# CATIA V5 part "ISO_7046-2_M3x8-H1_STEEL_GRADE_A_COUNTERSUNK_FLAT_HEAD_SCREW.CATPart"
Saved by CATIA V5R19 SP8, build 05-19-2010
Part number: ISO 7046-2 Vis M3x8-H1 Tête cruciforme fraisée à 90°
Definition: ISO 7046-2 Vis M3x8-H1 Tête cruciforme fraisée à 90°
Nomenclature: 70522
Publications: "Mating Edge", "Axis"
Bounding box of the stored display mesh (mm): x -8 to 0, y -2.741 to 2.741, z -2.75 to 2.75
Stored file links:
  D:\Documents\1_Travail\1 - ac-limoges.fr\ac-limoges.fr\Emmanuel Maynard - STI2D_Turgot\1 - IT-I2D\Activités_IT_Première\IT_3_Abris_bus\Maquettes numériques\Abribus_eleve\ISO_7046-2_M3x8-H1_STEEL_GRADE_A_COUNTERSUNK_FLAT_HEAD_SCREW.CATPart
  C:\MechanicalStandardParts\EN_Standards\Design_Tables\EN_ISO_7046-2_COUNTERSUNK_FLAT_HEAD_SCREW_CLASS_8_SERIES_1.txt
  C:\Program Files\Dassault Systemes\B19\win_b64\startup\components\MechanicalStandardParts\ISO_Standards\Design_Tables\ISO_7046_2_COUNTERSUNK_FLAT_HEAD_SCREW_CLASS_8_SERIES_1.txt
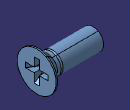
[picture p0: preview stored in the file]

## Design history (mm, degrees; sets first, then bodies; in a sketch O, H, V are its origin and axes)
Parameters
  d_dia = 3 mm
  Threading = 5.735 mm
  l_nom = 8 mm
  dk_nom = 5.5 mm
  k_max = 1.265 mm
  r_max = 0.8 mm
  Recess_width = 0.55 mm
  m_penetration_max = 2.1 mm
  P_pitch = 0.5 mm
  PartNumber = "ISO 7046-2 SCREW M3x8-H1 STEEL GRADE A COUNTERSUNK FLAT HEAD"
  m_ref = 3.2 mm
  Shank_dia = 2.97 mm
Body1 "PartBody" (main body)
  Sketch1 on zx-plane, origin (0, 0, 0), H (-1, 0, 0), V (0, 0, 1)
    line L1 (0, 0) -> (0, 2.75)
    line L2 (0, 2.75) -> (0.2, 2.75)
    point P2 (0.2, 2.75)
    line L3 (0.2, 2.75) -> (1.465, 1.485)
    line L4 (1.465, 1.485) -> (1.965, 1.485)
    point P4 (2.265, 1.4634)
    line L5 (2.265, 1.4634) -> (8, 1.4634)
    line L6 (8, 1.4634) -> (8, 0)
    line L7 (2.265, 1.4634) -> (2.015, 1.3375)
    line L8 (2.015, 1.3375) -> (1.965, 1.3375)
    line L9 (1.965, 1.3375) -> (1.965, 1.485)
    axis line L10 (-18.0862, 0) -> (75.7541, 0)
    distance P2 L1 = 0.2 {= P_pitch /2.5}
    distance P4 L6 = 5.735 {= Threading}
    distance L1 L6 = 8 {= l_nom}
    length L1 = 2.75 {= dk_nom /2}
    length L4 = 0.5 {= P_pitch}
    distance L4 H = 1.485 {= Shank_dia /2}
    distance L8 H = 1.3375 {= d_dia/2-(0.325*P_pitch )}
    length L7 H = 0.25 {= P_pitch /2}
    distance L5 L10 = 1.4634 {= d_dia /2.05}
    angle L3 L10 = 45
    vertical: L1 V, L6 V, L9 V
    horizontal: L2 H, L5 H, L10 H
    fix: L10
  Shaft1: profile Sketch1, axis Sketch1.L10, angle 360
  Body2
    Sketch2 on zx-plane, origin (0, 0, 0), H (-1, 0, 0), V (0, 0, 1)
      point P1 (2.1, 0)
      line L1 (0, 1.6) -> (0, -1.6)
      point P2 (0, 1.6)
      point P3 (0, -1.6)
      reference intersected line E1 through (1000000, 0) direction (-1, 0) from xy-plane
      reference projected line E2 (0, 9.15) -> (0, 8.0299) from edge [face of Shaft1 | face of Shaft1]
      line L2 (0, 1.6) -> (2.1, 0.275)
      point P4 (2.1, 0.275)
      line L3 (2.1, 0.275) -> (2.1, -0.275)
      point P5 (2.1, -0.275)
      line L4 (2.1, -0.275) -> (0, -1.6)
      distance O P1 = 2.1 {= m_penetration_max}
      distance P2 E1 = 1.6 {= m_ref /2}
      distance O P3 = 1.6 {= m_ref /2}
      distance P4 H = 0.275 {= Recess_width /2}
      distance P5 H = 0.275 {= Recess_width /2}
      vertical: L1 V, L3 V
      coincidence: L1 E2, L3 P1
    Pad1: profile Sketch2, direction (0, 1, 0), length 0.35, mirrored extent
    CircPattern1: of Pad1, instances 2, angular step 90, axis from face of Shaft1
  Remove1: tool Body2
  Thread1: diameter 2.9268 {= d_dia /1.025}, depth 5.735 {= Threading}, pitch 1, on face of Shaft1, from face of Shaft1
